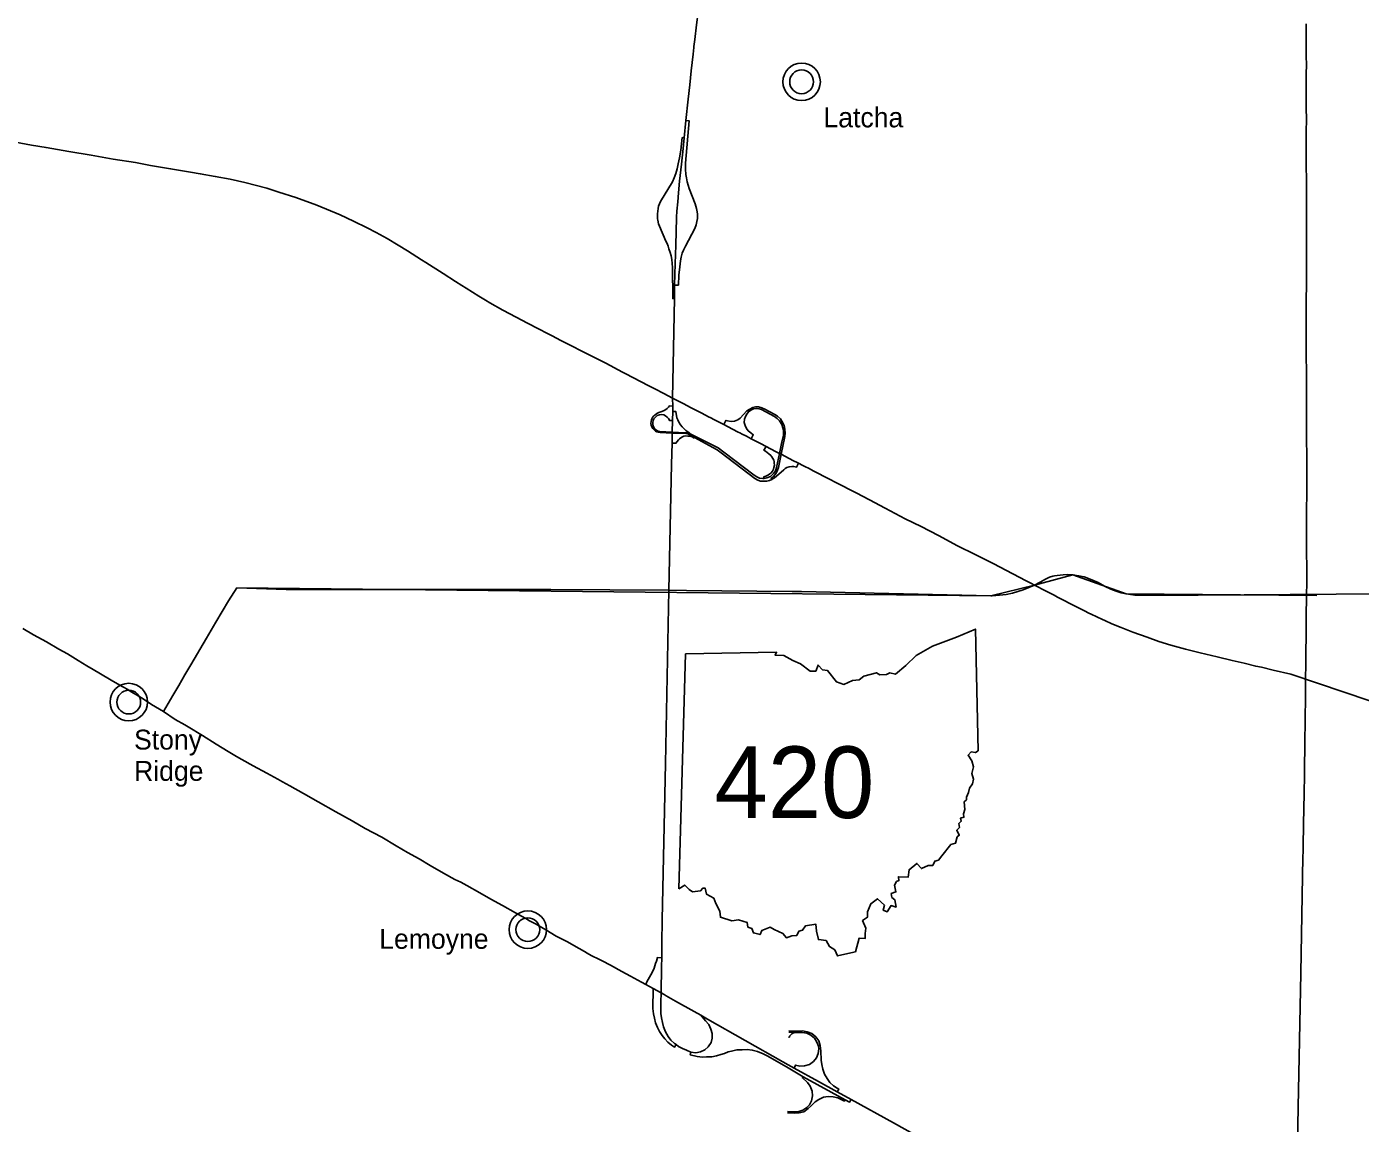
# Model space of a CAD drawing. Extents: x 0 to 851, y 0 to 440.
# Drawn here: x 378.43 to 425.25, y 277.34 to 315.84 of the extents above; entities that cross this region are included whole.
import ezdxf

# ---------------------------------------------------------------- set-up
doc = ezdxf.new("R2010")
doc.units = 0
for name, color, linetype in [('DV_X_Corp_Line', 7, 'Continuous'), ('GM_X_County', 7, 'Continuous'), ('GM_X_Interchange_Ramps', 7, 'Continuous'), ('GM_X_Interstate_Route', 7, 'Continuous'), ('GM_X_State_Route', 7, 'Continuous'), ('GM_X_US_Route', 7, 'Continuous'), ('PV_P_Text', 7, 'Continuous')]:
    doc.layers.add(name, color=color, linetype=linetype)

msp = doc.modelspace()

# ---------------------------------------------------------------- linework, layer by layer
at = {"layer": 'DV_X_Corp_Line'}
for centre, radius in [((405.635, 313.901), 0.658), ((405.635, 313.901), 0.417), ((382.013, 292.127), 0.658), ((382.013, 292.127), 0.417), ((396.023, 284.138), 0.658), ((396.023, 284.138), 0.417)]:
    msp.add_circle(centre, radius, dxfattribs=at)
at = {"layer": 'GM_X_County'}
msp.add_lwpolyline([(423.352, 315.933), (423.351, 315.684), (423.354, 315.121), (423.354, 314.948), (423.354, 314.758), (423.355, 314.542), (423.354, 314.139), (423.354, 313.81), (423.354, 313.605), (423.353, 313.068), (423.355, 312.49), (423.353, 312.243), (423.353, 311.776), (423.353, 311.088), (423.356, 310.318), (423.355, 309.824), (423.356, 309.329), (423.355, 308.889), (423.355, 307.789), (423.355, 306.91), (423.354, 306.112), (423.351, 305.59), (423.353, 305.221), (423.353, 305.15), (423.353, 304.772), (423.353, 304.655), (423.35, 304.218), (423.356, 303.776), (423.36, 303.116), (423.362, 302.429), (423.363, 302.016), (423.366, 301.384), (423.368, 300.752), (423.37, 299.377), (423.365, 298.939), (423.362, 298.086), (423.365, 297.22), (423.367, 297.013), (423.367, 296.738), (423.367, 296.298), (423.365, 295.902), (423.364, 295.803), (423.354, 295.172), (423.345, 294.376), (423.34, 293.962), (423.34, 293.768), (423.337, 293.357), (423.331, 293.052), (423.329, 292.99), (423.33, 292.929), (423.324, 292.5), (423.31, 291.331), (423.307, 290.864), (423.286, 289.565), (423.276, 288.935), (423.261, 287.836), (423.244, 287.052), (423.242, 286.885), (423.233, 286.689), (423.159, 282.61), (423.071, 277.904), (422.913, 269.421)], dxfattribs=at)
at = {"layer": 'GM_X_Interchange_Ramps'}
for points in [[(401.975, 309.129), (401.975, 309.259), (401.966, 309.335), (401.939, 309.455), (401.893, 309.618), (401.692, 310.159), (401.654, 310.27), (401.62, 310.393), (401.593, 310.526), (401.576, 310.649), (401.563, 310.832), (401.564, 311.047), (401.688, 312.526), (401.574, 312.539)], [(401.509, 311.938), (401.444, 311.944), (401.391, 311.498), (401.349, 311.23), (401.305, 311.026), (401.265, 310.841), (401.222, 310.683), (401.162, 310.525), (401.103, 310.387), (400.681, 309.703), (400.64, 309.614), (400.615, 309.532), (400.6, 309.456), (400.574, 309.271), (400.574, 309.128)], [(400.574, 309.128), (400.574, 309.094), (400.588, 309.039), (400.616, 308.92), (400.645, 308.837), (400.872, 308.308), (400.915, 308.222), (400.95, 308.133), (400.979, 308.037), (401.017, 307.91), (401.052, 307.787), (401.077, 307.66), (401.094, 307.517), (401.098, 307.387), (401.113, 306.293), (401.169, 306.292)], [(401.177, 306.765), (401.307, 306.763), (401.321, 307.11), (401.354, 307.402), (401.386, 307.62), (401.409, 307.742), (401.446, 307.881), (401.486, 307.996), (401.553, 308.131), (401.883, 308.754), (401.933, 308.879), (401.96, 308.994), (401.975, 309.101), (401.975, 309.129)], [(401.109, 302.514), (400.995, 302.523), (400.96, 302.476), (400.919, 302.437), (400.866, 302.398), (400.805, 302.363), (400.724, 302.331), (400.619, 302.292), (400.553, 302.258), (400.491, 302.213), (400.439, 302.162), (400.401, 302.117), (400.365, 302.049), (400.354, 301.973), (400.347, 301.909), (400.359, 301.847), (400.375, 301.794), (400.415, 301.728), (400.457, 301.685), (400.507, 301.64), (400.553, 301.616), (400.608, 301.599), (400.67, 301.589), (401.09, 301.571), (401.574, 301.55), (401.636, 301.538), (401.689, 301.515), (401.74, 301.487), (401.873, 301.418), (402.519, 301.063), (402.667, 300.976), (402.813, 300.872), (403.989, 299.971), (404.096, 299.913), (404.186, 299.885), (404.316, 299.878), (404.415, 299.885), (404.512, 299.91), (404.591, 299.944), (404.607, 299.951), (404.685, 299.998), (404.757, 300.055), (405.008, 300.284), (405.063, 300.329), (405.117, 300.359), (405.199, 300.39), (405.296, 300.401), (405.364, 300.395), (405.457, 300.374), (405.53, 300.511)], [(404.591, 299.944), (404.564, 299.983), (404.634, 300.037), (404.702, 300.11), (404.756, 300.191), (404.792, 300.268), (404.818, 300.364), (404.917, 300.826), (405.049, 301.45), (405.06, 301.564), (405.048, 301.712), (405.017, 301.835), (404.979, 301.927), (404.888, 302.068), (404.787, 302.158), (404.694, 302.226), (404.343, 302.413), (404.234, 302.46), (404.123, 302.486), (404.021, 302.488), (403.917, 302.465), (403.814, 302.413), (403.712, 302.345), (403.474, 302.099), (403.398, 302.039), (403.274, 301.987), (403.159, 301.977), (403.037, 301.995), (402.978, 302.015), (402.899, 301.868)], [(403.864, 301.372), (403.936, 301.512), (403.847, 301.582), (403.764, 301.65), (403.697, 301.733), (403.65, 301.839), (403.624, 301.946), (403.632, 302.055), (403.66, 302.148), (403.71, 302.239), (403.769, 302.317), (403.847, 302.376), (403.946, 302.418), (404.052, 302.428), (404.146, 302.418), (404.224, 302.395), (404.681, 302.156), (404.774, 302.083), (404.86, 302.005), (404.94, 301.873), (404.99, 301.72), (405, 301.621), (404.995, 301.496), (404.933, 301.203), (404.86, 300.856), (404.756, 300.362), (404.717, 300.248), (404.652, 300.146), (404.538, 300.045), (404.411, 299.993), (404.32, 299.976), (404.278, 299.972), (404.151, 299.988), (404.058, 300.03), (403.972, 300.089), (402.908, 300.899), (402.71, 301.048), (401.741, 301.534), (401.708, 301.547), (401.664, 301.565), (401.602, 301.58), (401.54, 301.582), (401.091, 301.603), (400.656, 301.623), (400.599, 301.64), (400.551, 301.664), (400.508, 301.693), (400.476, 301.729), (400.442, 301.775), (400.421, 301.823), (400.406, 301.887), (400.409, 301.944), (400.424, 302.006), (400.45, 302.073), (400.514, 302.142), (400.568, 302.183), (400.641, 302.215), (400.729, 302.218), (400.797, 302.206), (400.859, 302.172), (400.916, 302.131), (400.963, 302.083), (400.986, 302.052), (401.001, 302.008), (401.104, 302.007)], [(401.708, 301.547), (401.715, 301.564), (401.64, 301.611), (401.569, 301.663), (401.498, 301.727), (401.439, 301.789), (401.381, 301.862), (401.327, 301.948), (401.291, 302.029), (401.257, 302.107), (401.225, 302.322), (401.117, 302.327)], [(401.093, 301.219), (401.223, 301.214), (401.262, 301.279), (401.307, 301.335), (401.349, 301.373), (401.426, 301.426), (401.495, 301.456), (401.565, 301.468), (401.635, 301.465), (401.72, 301.456), (401.79, 301.436), (401.861, 301.392), (401.873, 301.418)], [(404.386, 301.101), (404.314, 300.969), (404.369, 300.936), (404.426, 300.893), (404.49, 300.845), (404.556, 300.782), (404.595, 300.732), (404.63, 300.674), (404.654, 300.622), (404.667, 300.575), (404.677, 300.513), (404.678, 300.442), (404.665, 300.367), (404.644, 300.303), (404.608, 300.236), (404.561, 300.179), (404.504, 300.127), (404.453, 300.095), (404.383, 300.061), (404.313, 300.038), (404.32, 299.976)], [(400.727, 283.152), (400.571, 283.158), (400.539, 283.033), (400.511, 282.953), (400.455, 282.79), (400.383, 282.633), (400.298, 282.471), (400.202, 282.306), (400.165, 282.217)], [(400.429, 282.07), (400.429, 281.952), (400.411, 281.475), (400.411, 281.366), (400.434, 281.18), (400.465, 281.035), (400.511, 280.863), (400.574, 280.699), (400.651, 280.568), (400.738, 280.427), (400.828, 280.309), (400.934, 280.194), (401.064, 280.08), (401.17, 280.012), (401.233, 280.104)], [(405.18, 280.369), (405.207, 280.369), (405.226, 280.408), (405.257, 280.447), (405.297, 280.481), (405.331, 280.501), (405.373, 280.517), (405.373, 280.532)], [(406.883, 278.446), (406.94, 278.54), (406.886, 278.577), (406.752, 278.66), (406.623, 278.776), (406.532, 278.91), (406.444, 279.064), (406.382, 279.235), (406.348, 279.401), (406.327, 279.56), (406.307, 279.885), (406.286, 280.072), (406.236, 280.235), (406.132, 280.38), (405.998, 280.489), (405.832, 280.555), (405.669, 280.584), (405.257, 280.58), (405.182, 280.584)], [(405.183, 280.534), (405.258, 280.534), (405.373, 280.532), (405.656, 280.524), (405.741, 280.517), (405.82, 280.501), (405.892, 280.471), (405.963, 280.43), (406.087, 280.329), (406.17, 280.194), (406.226, 280.047), (406.235, 279.958), (406.216, 279.79), (406.156, 279.634), (406.048, 279.504), (405.911, 279.408), (405.739, 279.358), (405.577, 279.344), (405.575, 279.344), (405.418, 279.381), (405.375, 279.278)], [(401.751, 279.842), (401.724, 279.743), (401.974, 279.685), (402.153, 279.664), (402.299, 279.668), (402.478, 279.676), (402.649, 279.71), (402.803, 279.76), (402.924, 279.793), (403.061, 279.847), (403.174, 279.876), (403.357, 279.918), (403.549, 279.922), (403.728, 279.93), (403.903, 279.91), (404.082, 279.864), (404.29, 279.78), (404.453, 279.701), (405.165, 279.287), (405.694, 278.976), (407.169, 278.164), (407.32, 278.085), (407.37, 278.176)], [(405.694, 278.976), (405.661, 278.931), (405.844, 278.768), (405.94, 278.639), (406.002, 278.468), (406.019, 278.31), (405.986, 278.131), (405.907, 277.989), (405.823, 277.893), (405.682, 277.797), (405.54, 277.752), (405.407, 277.743), (405.194, 277.747), (405.144, 277.75)], [(405.143, 277.702), (405.203, 277.702), (405.373, 277.693), (405.544, 277.702), (405.711, 277.747), (405.861, 277.86), (405.982, 277.968), (406.111, 278.089), (406.24, 278.181), (406.407, 278.256), (406.573, 278.277), (406.74, 278.272), (406.911, 278.235), (407.048, 278.168), (407.14, 278.122), (407.169, 278.164)]]:
    msp.add_lwpolyline(points, dxfattribs=at)
at = {"layer": 'GM_X_Interstate_Route'}
for points in [[(401.85, 315.108), (401.854, 315.139), (401.881, 315.387), (401.94, 315.895), (401.998, 316.351), (402.065, 316.957), (402.1, 317.386), (402.152, 317.865), (402.199, 318.303), (402.233, 318.719), (402.277, 319.09), (402.315, 319.539), (402.356, 320.022), (402.409, 320.524), (402.457, 321.01), (402.506, 321.506), (402.562, 322.019), (402.565, 322.043), (402.624, 322.537), (402.696, 322.996)], [(401.107, 302.798), (401.169, 306.292), (401.177, 306.765), (401.194, 307.515), (401.222, 308.168), (401.234, 308.648), (401.245, 309.129), (401.246, 309.154), (401.256, 309.365), (401.285, 309.687), (401.311, 309.998), (401.352, 310.417), (401.416, 311.013), (401.472, 311.556), (401.509, 311.938), (401.574, 312.539), (401.657, 313.29), (401.709, 313.789), (401.761, 314.291), (401.825, 314.874), (401.85, 315.108)], [(378.035, 311.783), (378.598, 311.679), (379.111, 311.589), (379.904, 311.457), (380.691, 311.32), (381.465, 311.185), (382.251, 311.064), (382.78, 310.967), (383.481, 310.849), (384.177, 310.731), (384.525, 310.672), (385.047, 310.581), (385.569, 310.478), (386.087, 310.362), (386.855, 310.164), (387.281, 310.031), (387.88, 309.836), (388.611, 309.571), (389.429, 309.226), (389.908, 309.007), (390.383, 308.77), (390.698, 308.607), (391.086, 308.396), (391.47, 308.168), (391.801, 307.964), (392.294, 307.656), (392.445, 307.559), (393.049, 307.174), (393.483, 306.891), (393.707, 306.755), (393.857, 306.655), (394.308, 306.375), (394.536, 306.23), (394.687, 306.145), (395.147, 305.884), (395.617, 305.634), (396.01, 305.429), (396.402, 305.229), (396.717, 305.067), (396.876, 304.984), (397.187, 304.824), (397.58, 304.618), (397.895, 304.456), (398.525, 304.137), (398.758, 304.019), (399.351, 303.705)], [(399.351, 303.705), (399.465, 303.645), (400.246, 303.239), (400.483, 303.121), (400.798, 302.959), (401.107, 302.798)], [(401.107, 302.798), (401.294, 302.699), (401.501, 302.591), (401.738, 302.466), (402.131, 302.267), (402.364, 302.142), (402.446, 302.104), (402.548, 302.049), (402.899, 301.868), (403.06, 301.786)], [(403.06, 301.786), (403.386, 301.618), (403.489, 301.565), (403.52, 301.549), (403.701, 301.456), (403.864, 301.372), (404.196, 301.2), (404.386, 301.101), (404.724, 300.926), (404.86, 300.856), (404.917, 300.826), (405.194, 300.683), (405.353, 300.601), (405.479, 300.537), (405.53, 300.511), (405.677, 300.434), (405.746, 300.402), (405.901, 300.321), (406.035, 300.25), (406.609, 299.953), (406.842, 299.835), (407.549, 299.467), (408.024, 299.224), (408.569, 298.929), (409.276, 298.564), (409.829, 298.294), (410.446, 297.971), (411.11, 297.616), (411.724, 297.31), (412.358, 296.987), (413.047, 296.624), (413.521, 296.381), (413.677, 296.3), (413.813, 296.231)], [(413.813, 296.231), (414.225, 296.02), (414.504, 295.874), (414.617, 295.814), (415.281, 295.473), (415.563, 295.328), (415.722, 295.253), (415.8, 295.209), (416.202, 295.022), (416.28, 294.985), (416.526, 294.878), (416.851, 294.747), (417.263, 294.584), (417.761, 294.401), (418.182, 294.257), (418.603, 294.124), (419.111, 293.984), (419.628, 293.851), (420.228, 293.71), (420.746, 293.589), (421.176, 293.487), (421.581, 293.384), (421.781, 293.347), (422.188, 293.249), (422.811, 293.104), (433.003, 289.671)]]:
    msp.add_lwpolyline(points, dxfattribs=at)
at = {"layer": 'GM_X_State_Route'}
for points in [[(400.745, 284.479), (400.855, 289.966), (400.974, 296.05), (401.066, 300.483), (401.093, 301.219), (401.09, 301.571), (401.091, 301.603), (401.104, 302.007), (401.117, 302.327), (401.109, 302.514), (401.107, 302.798)], [(385.808, 296.134), (412.274, 295.858), (413.813, 296.231), (413.813, 296.231), (415.16, 296.589), (417.033, 295.922), (423.728, 295.872)], [(412.274, 295.858), (412.321, 295.857), (412.583, 295.876), (412.811, 295.899), (413.036, 295.952), (413.225, 296.009), (413.415, 296.07), (413.612, 296.15), (413.813, 296.231), (414.01, 296.341), (414.196, 296.445), (414.335, 296.506), (414.459, 296.541), (414.519, 296.553), (414.604, 296.569), (414.812, 296.595), (414.959, 296.603), (415.16, 296.589), (415.357, 296.562), (415.554, 296.519), (415.823, 296.423), (416.042, 296.322), (416.298, 296.183), (416.49, 296.093), (416.68, 296.019), (416.859, 295.962), (417.033, 295.922), (417.176, 295.903), (417.33, 295.88), (418.043, 295.878)], [(383.228, 291.794), (383.556, 292.353), (383.776, 292.709), (383.981, 293.078), (384.197, 293.44), (384.739, 294.375), (385.068, 294.93), (385.517, 295.682), (385.808, 296.134), (387.538, 296.083), (388.001, 296.078), (393.132, 296.079)], [(393.132, 296.079), (395.078, 296.079)], [(395.078, 296.079), (396.493, 296.079), (396.825, 296.079), (400.974, 296.05)], [(400.974, 296.05), (401.592, 296.044)], [(401.592, 296.044), (405.3, 296.01), (405.631, 296.003)], [(405.631, 296.003), (412.274, 295.858)], [(418.043, 295.878), (419.56, 295.875), (438.954, 296.017)], [(400.72, 282.85), (400.727, 283.152), (400.728, 283.669), (400.745, 284.479)], [(402.094, 281.134), (402.261, 280.939), (402.377, 280.806), (402.453, 280.649), (402.5, 280.498), (402.495, 280.334), (402.454, 280.176), (402.36, 280.029), (402.238, 279.923), (402.084, 279.851), (401.916, 279.819), (401.751, 279.842), (401.594, 279.907), (401.45, 279.968), (401.317, 280.042), (401.233, 280.104), (401.168, 280.145), (401.048, 280.259), (400.953, 280.392), (400.855, 280.553), (400.787, 280.73), (400.75, 280.879), (400.716, 281.038), (400.697, 281.197), (400.691, 281.36), (400.688, 281.591), (400.702, 281.916), (400.72, 282.85)]]:
    msp.add_lwpolyline(points, dxfattribs=at)
at = {"layer": 'GM_X_US_Route'}
for points in [[(378.29, 294.708), (378.668, 294.493)], [(378.668, 294.493), (379.13, 294.247)], [(379.13, 294.247), (379.557, 293.987), (379.864, 293.82), (380.233, 293.586), (380.543, 293.395), (380.76, 293.272), (381.022, 293.123), (381.39, 292.901), (381.698, 292.724), (381.799, 292.665), (381.98, 292.563), (382.098, 292.492), (382.29, 292.386), (382.402, 292.312)], [(382.402, 292.312), (382.48, 292.26), (382.812, 292.04), (383.228, 291.794), (383.642, 291.516), (383.977, 291.325)], [(383.977, 291.325), (384.099, 291.256), (384.603, 290.955), (385.08, 290.655), (385.5, 290.396), (385.795, 290.22), (385.981, 290.116), (386.379, 289.894), (386.86, 289.634), (387.247, 289.416), (387.415, 289.324), (387.668, 289.184), (388.142, 288.914), (388.66, 288.62), (389.28, 288.274), (389.85, 287.955), (390.317, 287.692), (390.898, 287.38), (391.399, 287.084), (391.797, 286.844), (392.209, 286.619), (392.6, 286.388), (393.057, 286.126), (393.459, 285.901), (393.669, 285.809)], [(393.669, 285.809), (393.883, 285.688), (394.338, 285.433), (394.723, 285.209), (395.13, 284.989), (395.586, 284.734), (395.803, 284.613), (395.952, 284.528), (396.083, 284.452), (396.316, 284.325), (396.658, 284.131), (397.022, 283.912), (397.389, 283.72), (397.822, 283.473), (398.014, 283.368), (398.109, 283.313)], [(398.109, 283.313), (398.246, 283.234), (398.538, 283.096), (398.636, 283.044)], [(398.636, 283.044), (398.929, 282.888), (399.326, 282.667), (399.629, 282.505)], [(399.629, 282.505), (400.012, 282.299)], [(400.012, 282.299), (400.165, 282.217), (400.429, 282.07), (400.702, 281.916), (400.805, 281.856)], [(400.805, 281.856), (400.88, 281.812)], [(400.88, 281.812), (401.202, 281.624), (401.864, 281.266), (402.094, 281.134), (402.334, 280.998)], [(402.334, 280.998), (404.973, 279.502)], [(404.973, 279.502), (405.167, 279.393), (405.375, 279.278), (406.232, 278.806), (406.883, 278.446), (407.37, 278.176), (408.856, 277.353), (410.162, 276.629)]]:
    msp.add_lwpolyline(points, dxfattribs=at)
at = {"layer": 'PV_P_Text'}
msp.add_line((401.323, 285.576), (401.554, 293.824), dxfattribs=at)
msp.add_line((401.323, 285.576), (401.554, 293.824), dxfattribs=at)
for points in [[(401.554, 293.824), (404.754, 293.878), (404.704, 293.778), (405.006, 293.757), (405.327, 293.581), (405.598, 293.47), (405.93, 293.207), (406.129, 293.21), (406.213, 293.425), (406.365, 293.259), (406.545, 293.23), (406.857, 292.835), (407.115, 292.749), (407.423, 292.885), (407.654, 292.907), (407.822, 293.041), (408.261, 293.155), (408.384, 293.087), (408.616, 293.1), (408.733, 293.151), (408.936, 293.106), (409.293, 293.406), (409.66, 293.759), (410.226, 294.093), (411.07, 294.409), (411.737, 294.692), (411.834, 290.411)], [(401.554, 293.824), (404.754, 293.878), (404.704, 293.778), (405.006, 293.757), (405.327, 293.581), (405.598, 293.47), (405.93, 293.207), (406.129, 293.21), (406.213, 293.425), (406.365, 293.259), (406.545, 293.23), (406.857, 292.835), (407.115, 292.749), (407.423, 292.885), (407.654, 292.907), (407.822, 293.041), (408.261, 293.155), (408.384, 293.087), (408.616, 293.1), (408.733, 293.151), (408.936, 293.106), (409.293, 293.406), (409.66, 293.759), (410.226, 294.093), (411.07, 294.409), (411.737, 294.692), (411.834, 290.411)], [(411.834, 290.411), (411.735, 290.351), (411.582, 290.38), (411.479, 290.26), (411.606, 290.059), (411.667, 289.848), (411.613, 289.614), (411.666, 289.422), (411.63, 289.261), (411.534, 289.101), (411.5, 288.948), (411.419, 288.787), (411.425, 288.697), (411.347, 288.626), (411.361, 288.358), (411.322, 288.209), (411.335, 288.082), (411.209, 288.048), (411.238, 287.942), (411.157, 287.861), (411.174, 287.72), (411.083, 287.63), (411.172, 287.451), (411.101, 287.394), (411.041, 287.175), (410.879, 287.131), (410.553, 286.732), (410.439, 286.581), (410.31, 286.543), (410.238, 286.388), (410.08, 286.387), (409.839, 286.28), (409.684, 286.465), (409.411, 286.242), (409.38, 285.985), (409.036, 285.993), (409.049, 285.863), (408.972, 285.825), (408.902, 285.695), (408.943, 285.464), (408.782, 285.405), (408.801, 285.27), (408.905, 285.188), (408.951, 284.931), (408.779, 284.983), (408.639, 284.767), (408.495, 284.818), (408.542, 285.001), (408.298, 285.221), (408.067, 285.045), (407.947, 284.763), (407.946, 284.573), (407.774, 284.458), (407.884, 284.19), (407.864, 284.005), (407.867, 283.83), (407.652, 283.836), (407.522, 283.362)], [(411.834, 290.411), (411.735, 290.351), (411.582, 290.38), (411.479, 290.26), (411.606, 290.059), (411.667, 289.848), (411.613, 289.614), (411.666, 289.422), (411.63, 289.261), (411.534, 289.101), (411.5, 288.948), (411.419, 288.787), (411.425, 288.697), (411.347, 288.626), (411.361, 288.358), (411.322, 288.209), (411.335, 288.082), (411.209, 288.048), (411.238, 287.942), (411.157, 287.861), (411.174, 287.72), (411.083, 287.63), (411.172, 287.451), (411.101, 287.394), (411.041, 287.175), (410.879, 287.131), (410.553, 286.732), (410.439, 286.581), (410.31, 286.543), (410.238, 286.388), (410.08, 286.387), (409.839, 286.28), (409.684, 286.465), (409.411, 286.242), (409.38, 285.985), (409.036, 285.993), (409.049, 285.863), (408.972, 285.825), (408.902, 285.695), (408.943, 285.464), (408.782, 285.405), (408.801, 285.27), (408.905, 285.188), (408.951, 284.931), (408.779, 284.983), (408.639, 284.767), (408.495, 284.818), (408.542, 285.001), (408.298, 285.221), (408.067, 285.045), (407.947, 284.763), (407.946, 284.573), (407.774, 284.458), (407.884, 284.19), (407.864, 284.005), (407.867, 283.83), (407.652, 283.836), (407.522, 283.362)], [(407.522, 283.362), (407.149, 283.272), (406.89, 283.217), (406.798, 283.433), (406.613, 283.546), (406.492, 283.763), (406.226, 283.792), (406.163, 284.089), (406.133, 284.331), (405.769, 284.271), (405.669, 284.124), (405.54, 284.084), (405.465, 283.935), (405.289, 283.923), (405.1, 283.853), (404.977, 283.999), (404.667, 284.145), (404.528, 284.221), (404.237, 284.103), (404.175, 283.964), (403.944, 284.026), (403.89, 284.181), (403.75, 284.227), (403.719, 284.391), (403.419, 284.479), (403.19, 284.444), (402.786, 284.576), (402.762, 284.792), (402.624, 285.056), (402.552, 285.239), (402.297, 285.378), (402.245, 285.596), (402.163, 285.589), (402.089, 285.501), (401.805, 285.46), (401.692, 285.549), (401.533, 285.701), (401.323, 285.576)], [(407.522, 283.362), (407.149, 283.272), (406.89, 283.217), (406.798, 283.433), (406.613, 283.546), (406.492, 283.763), (406.226, 283.792), (406.163, 284.089), (406.133, 284.331), (405.769, 284.271), (405.669, 284.124), (405.54, 284.084), (405.465, 283.935), (405.289, 283.923), (405.1, 283.853), (404.977, 283.999), (404.667, 284.145), (404.528, 284.221), (404.237, 284.103), (404.175, 283.964), (403.944, 284.026), (403.89, 284.181), (403.75, 284.227), (403.719, 284.391), (403.419, 284.479), (403.19, 284.444), (402.786, 284.576), (402.762, 284.792), (402.624, 285.056), (402.552, 285.239), (402.297, 285.378), (402.245, 285.596), (402.163, 285.589), (402.089, 285.501), (401.805, 285.46), (401.692, 285.549), (401.533, 285.701), (401.323, 285.576)]]:
    msp.add_lwpolyline(points, dxfattribs=at)

# ---------------------------------------------------------------- texts
at = {"layer": 'DV_X_Corp_Line'}
for s, p in [('Latcha', (406.402, 312.302)), ('Stony', (382.198, 290.46)), ('Ridge', (382.198, 289.362)), ('Lemoyne', (390.806, 283.466))]:
    msp.add_text(s, height=0.6979, rotation=0, dxfattribs=at).set_placement(p)
at = {"layer": 'PV_P_Text'}
msp.add_text('420', height=2.5126, dxfattribs=at).set_placement((402.581, 288.057))

doc.saveas('drawing.dxf')
